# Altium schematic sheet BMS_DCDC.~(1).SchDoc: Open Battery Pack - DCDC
size A3; Date: 26/03/2019; Author: Morgane Vallée - Samuel Lesueur; Revision: 1.0; SheetNumber: 2; SheetTotal: 4
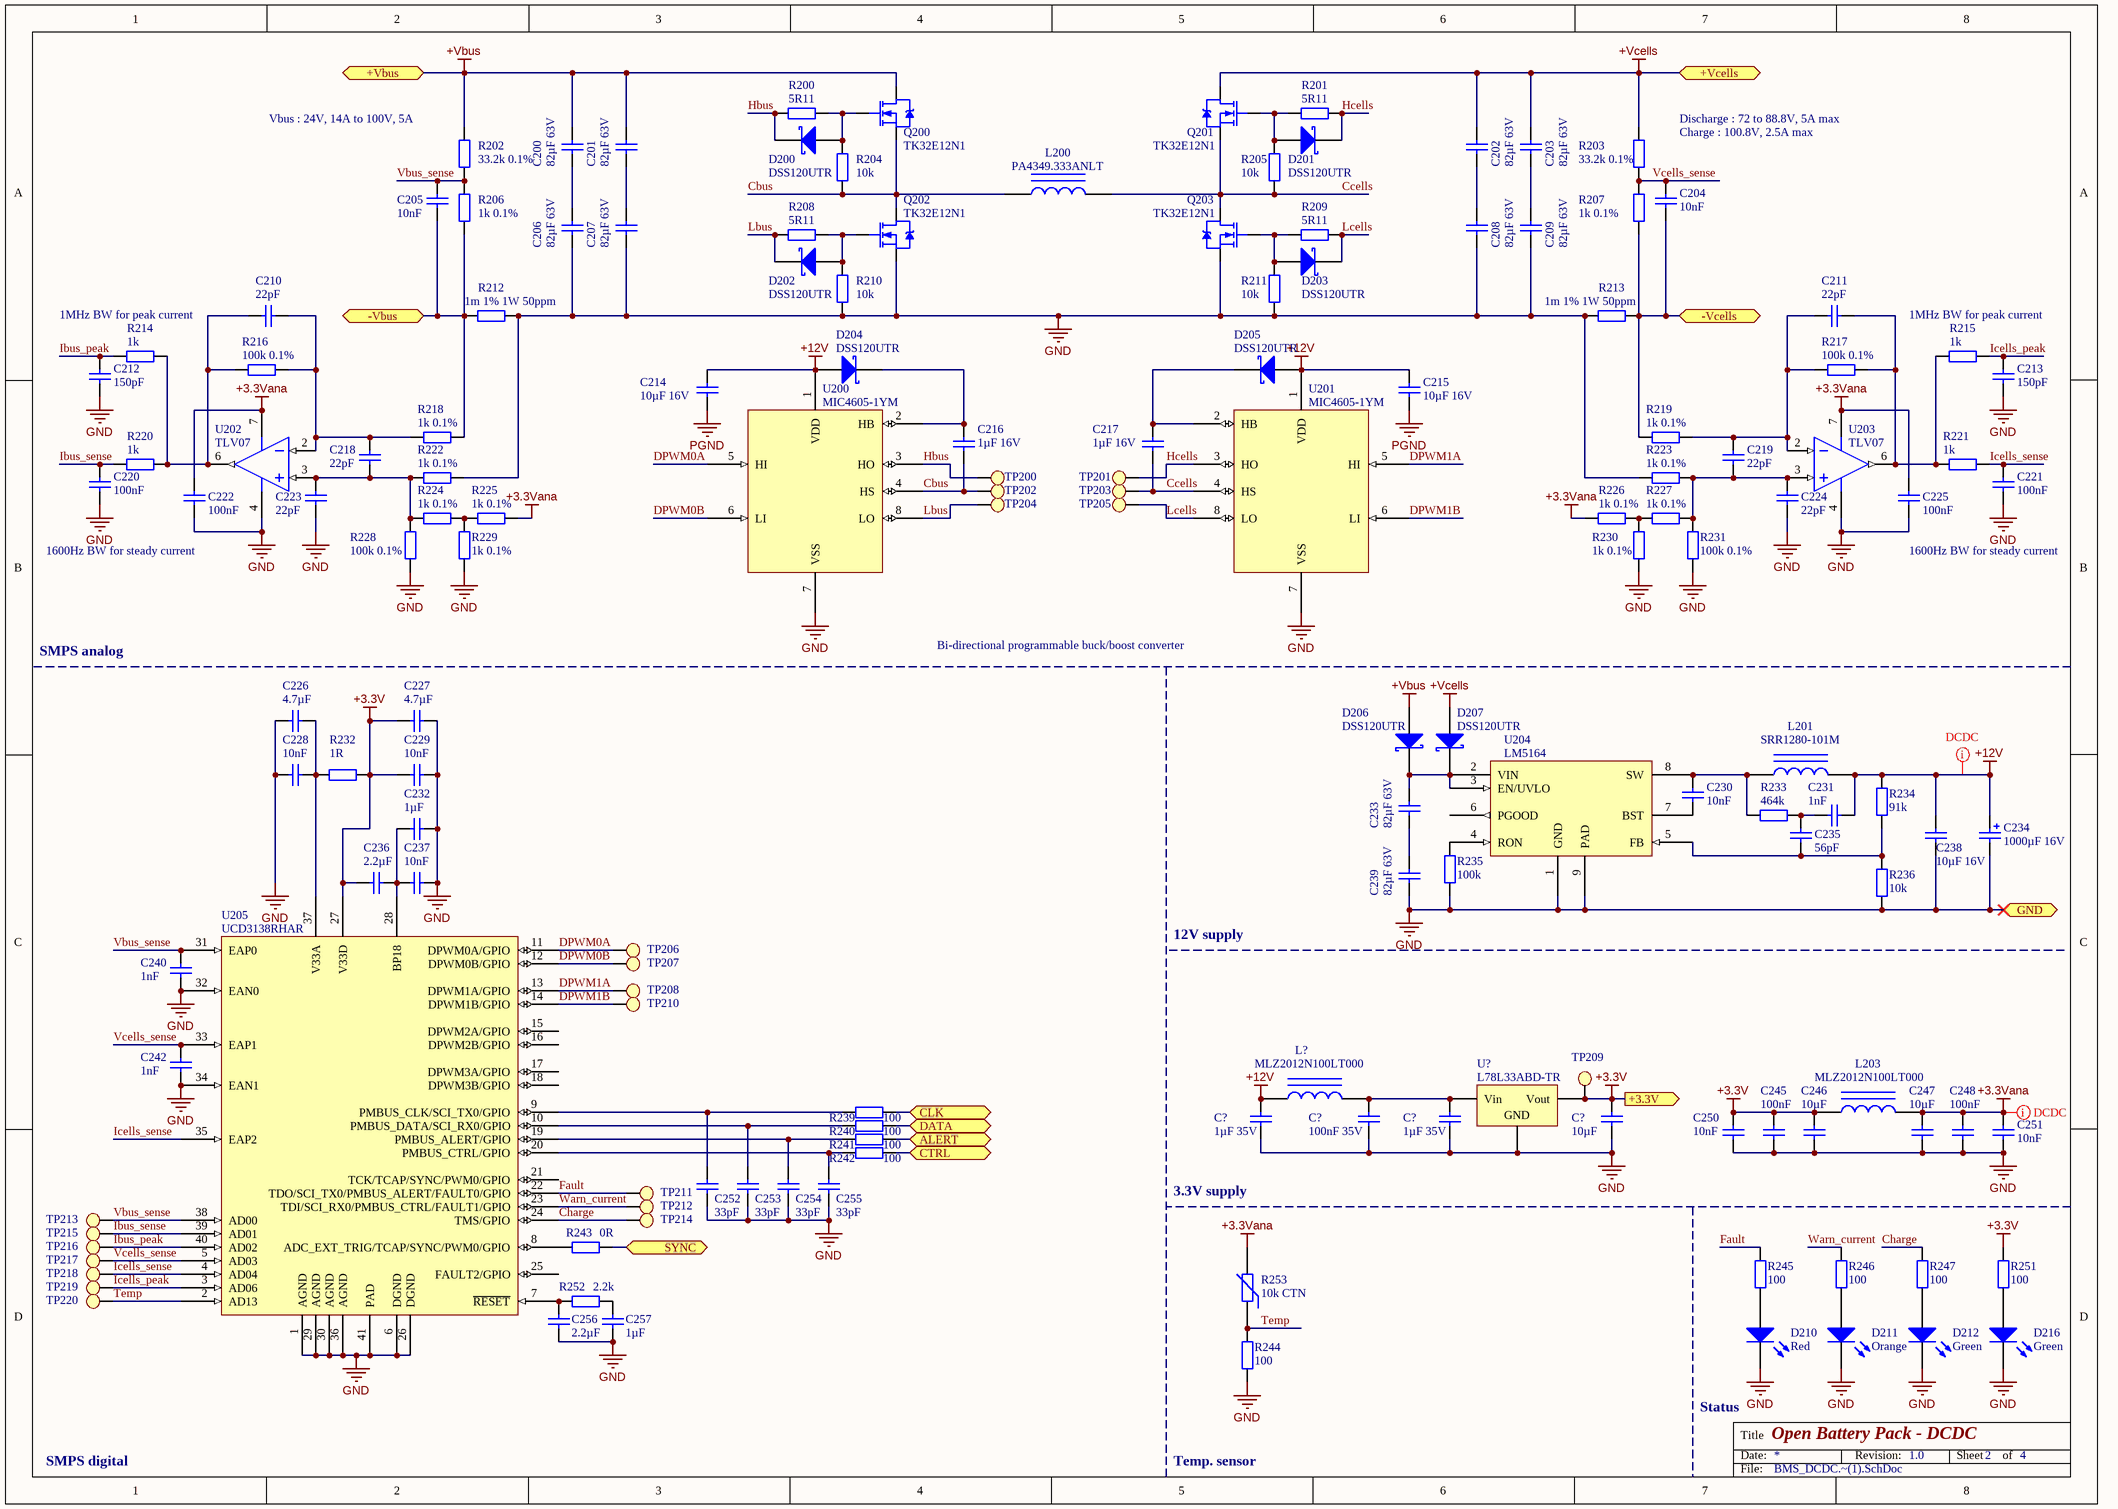
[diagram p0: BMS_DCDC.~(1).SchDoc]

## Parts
(Parts that share a designator on the sheet are numbered #1, #2 ... from top to bottom, then left to right.)
C200  82µF 63V  [CAP ALUM 10.3MM]
C201  82µF 63V  [CAP ALUM 10.3MM]
C202  82µF 63V  [CAP ALUM 10.3MM]
C203  82µF 63V  [CAP ALUM 10.3MM]
C204  10nF  [C0603]
C205  10nF  [C0603]
C206  82µF 63V  [CAP ALUM 10.3MM]
C207  82µF 63V  [CAP ALUM 10.3MM]
C208  82µF 63V  [CAP ALUM 10.3MM]
C209  82µF 63V  [CAP ALUM 10.3MM]
C210  22pF  [C0603]
C211  22pF  [C0603]
C212  150pF  [C0603]
C213  150pF  [C0603]
C214  10µF 16V  [C0805]
C215  10µF 16V  [C0805]
C216  1µF 16V  [C0603]
C217  1µF 16V  [C0603]
C218  22pF  [C0603]
C219  22pF  [C0603]
C220  100nF  [C0603]
C221  100nF  [C0603]
C222  100nF  [C0603]
C223  22pF  [C0603]
C224  22pF  [C0603]
C225  100nF  [C0603]
C226  4.7µF  [C0603]
C227  4.7µF  [C0603]
C228  10nF  [C0603]
C229  10nF  [C0603]
C230  10nF  [C0603]
C231  1nF  [C0603]
C232  1µF  [C0603]
C233  82µF 63V  [CAP ALUM 10.3MM]
C234  1000µF 16V  [CAP AL TH D10 L5 H17.5]
C235  56pF  [C0603]
C236  2.2µF  [C0603]
C237  10nF  [C0603]
C238  10µF 16V  [C0805]
C239  82µF 63V  [CAP ALUM 10.3MM]
C240  1nF  [C0603]
C242  1nF  [C0603]
C245  100nF  [C0603]
C246  10µF  [C0603]
C247  10µF  [C0603]
C248  100nF  [C0603]
C250  10nF  [C0603]
C251  10nF  [C0603]
C252  33pF  [C0603]
C253  33pF  [C0603]
C254  33pF  [C0603]
C255  33pF  [C0603]
C256  2.2µF  [C0603]
C257  1µF  [C0603]
C?#1  1µF 35V  [C0805]
C?#2  100nF 35V  [C0603]
C?#3  1µF 35V  [C0805]
C?#4  10µF  [C0603]
D200  DSS120UTR  [SOD123F]
D201  DSS120UTR  [SOD123F]
D202  DSS120UTR  [SOD123F]
D203  DSS120UTR  [SOD123F]
D204  DSS120UTR  [SOD123F]
D205  DSS120UTR  [SOD123F]
D206  DSS120UTR  [SOD123F]
D207  DSS120UTR  [SOD123F]
D210  Red  [LED 0603/1608]
D211  Orange  [LED 0603/1608]
D212  Green  [LED 0603/1608]
D216  Green  [LED 0603/1608]
L200  PA4349.333ANLT  [SELF_SMD_23.5x22]
L201  SRR1280-101M  [SELF_SMD_12.5x12.5]
L203  MLZ2012N100LT000  [C0805]
L?  MLZ2012N100LT000  [FER 0805/2012]
Q200  TK32E12N1  [TO220]
Q201  TK32E12N1  [TO220]
Q202  TK32E12N1  [TO220]
Q203  TK32E12N1  [TO220]
R200  5R11  [R0603]
R201  5R11  [R0603]
R202  33.2k 0.1%  [R0603]
R203  33.2k 0.1%  [R0603]
R204  10k  [R0603]
R205  10k  [R0603]
R206  1k 0.1%  [R0603]
R207  1k 0.1%  [R0603]
R208  5R11  [R0603]
R209  5R11  [R0603]
R210  10k  [R0603]
R211  10k  [R0603]
R212  1m 1% 1W 50ppm  [R1206]
R213  1m 1% 1W 50ppm  [R1206]
R214  1k  [R0603]
R215  1k  [R0603]
R216  100k 0.1%  [R0603]
R217  100k 0.1%  [R0603]
R218  1k 0.1%  [R0603]
R219  1k 0.1%  [R0603]
R220  1k  [R0603]
R221  1k  [R0603]
R222  1k 0.1%  [R0603]
R223  1k 0.1%  [R0603]
R224  1k 0.1%  [R0603]
R225  1k 0.1%  [R0603]
R226  1k 0.1%  [R0603]
R227  1k 0.1%  [R0603]
R228  100k 0.1%  [R0603]
R229  1k 0.1%  [R0603]
R230  1k 0.1%  [R0603]
R231  100k 0.1%  [R0603]
R232  1R  [R0603]
R233  464k  [R0603]
R234  91k  [R0603]
R235  100k  [R0603]
R236  10k  [R0603]
R239  100  [R0603]
R240  100  [R0603]
R241  100  [R0603]
R242  100  [R0603]
R243  0R  [R0603]
R244  100  [R0603]
R245  100  [R0603]
R246  100  [R0603]
R247  100  [R0603]
R251  100  [R0603]
R252  2.2k  [R0603]
R253  10k CTN  [R0603]
TP200  Test Point  [Test Point]  (value not drawn)
TP201  Test Point  [Test Point]  (value not drawn)
TP202  Test Point  [Test Point]  (value not drawn)
TP203  Test Point  [Test Point]  (value not drawn)
TP204  Test Point  [Test Point]  (value not drawn)
TP205  Test Point  [Test Point]  (value not drawn)
TP206  Test Point  [Test Point]  (value not drawn)
TP207  Test Point  [Test Point]  (value not drawn)
TP208  Test Point  [Test Point]  (value not drawn)
TP209  Test Point  [Test Point]  (value not drawn)
TP210  Test Point  [Test Point]  (value not drawn)
TP211  Test Point  [Test Point]  (value not drawn)
TP212  Test Point  [Test Point]  (value not drawn)
TP213  Test Point  [Test Point]  (value not drawn)
TP214  Test Point  [Test Point]  (value not drawn)
TP215  Test Point  [Test Point]  (value not drawn)
TP216  Test Point  [Test Point]  (value not drawn)
TP217  Test Point  [Test Point]  (value not drawn)
TP218  Test Point  [Test Point]  (value not drawn)
TP219  Test Point  [Test Point]  (value not drawn)
TP220  Test Point  [Test Point]  (value not drawn)
U200  MIC4605-1YM  [SOIC-8]
U201  MIC4605-1YM  [SOIC-8]
U202  TLV07  [SOIC-8]
U203  TLV07  [SOIC-8]
U204  LM5164  [R-PDSO-G8]
U205  UCD3138RHAR  [S-PVQFN-N40]
U?  L78L33ABD-TR  [ST SOIC-8N]

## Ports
+3.3V, +Vbus, +Vcells, -Vbus, -Vcells, ALERT (bidir), CLK (bidir), CTRL (bidir), DATA (bidir), GND, SYNC (bidir)

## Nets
+3.3V: C227.1 C229.1 C236.2 C245.1 C246.1 C250.1 C?#4.1 L203.1 R232.1 R251.1 TP209.1 U205.27(V33D) U?.3(Vout) ; port +3.3V
+3.3Vana: C222.1 C225.1 C247.1 C248.1 C251.1 L203.2 R225.1 R226.1 R253.2 U202.7(V+) U203.7(V+)
+12V: C214.2 C215.2 C231.2 C234.1 C238.1 C?#1.1 D204.1(A) D205.1(A) L201.2 L?.1 R234.1 U200.1(VDD) U201.1(VDD)
+Vbus: C200.2 C201.2 D206.1(A) Q200.3(D) R202.1 ; port +Vbus
+Vcells: C202.2 C203.2 D207.1(A) Q201.3(D) R203.1 ; port +Vcells
GND: C206.1 C207.1 C208.1 C209.1 C212.1 C213.1 C220.1 C221.1 C222.2 C223.1 C224.1 C225.2 C226.1 C227.2 C228.1 C229.2 C232.1 C234.2 C237.1 C238.2 C239.2 C240.2 C242.2 C245.2 C246.2 C247.2 C248.2 C250.2 C251.2 C252.2 C253.2 C254.2 C255.2 C256.2 C257.2 C?#1.2 C?#2.2 C?#3.2 C?#4.2 D210.2(K) D211.2(K) D212.2(K) D216.2(K) Q202.2(S) Q203.2(S) R210.2 R211.2 R212.1 R213.2 R222.1 R223.2 R228.2 R229.2 R230.2 R231.2 R235.2 R236.2 R244.2 U200.7(VSS) U201.7(VSS) U202.4(V-) U203.4(V-) U204.1(GND) U204.9(PAD) U205.1(AGND) U205.6(DGND) U205.26(DGND) U205.29(AGND) U205.30(AGND) U205.32(EAN0) U205.34(EAN1) U205.36(AGND) U205.41(PAD) U?.2(GND) ; port GND
PGND: C214.1 C215.1
-Vbus: C205.1 R206.2 R212.2 R218.1 ; port -Vbus
-Vcells: C204.1 R207.2 R213.1 R219.2 ; port -Vcells
ALERT: R241.2 ; port ALERT
Cbus: C216.1 L200.1 Q200.2(S) Q202.3(D) R204.2 TP202.1 U200.4(HS)
Ccells: C217.1 L200.2 Q201.2(S) Q203.3(D) R205.2 TP203.1 U201.4(HS)
Charge: R247.1 TP214.1 U205.24(TMS/GPIO)
CLK: R239.2 ; port CLK
CTRL: R242.2 ; port CTRL
DATA: R240.2 ; port DATA
DPWM0A: TP206.1 U200.5(HI) U205.11(DPWM0A/GPIO)
DPWM0B: TP207.1 U200.6(LI) U205.12(DPWM0B/GPIO)
DPWM1A: TP208.1 U201.5(HI) U205.13(DPWM1A/GPIO)
DPWM1B: TP210.1 U201.6(LI) U205.14(DPWM1B/GPIO)
Fault: R245.1 TP211.1 U205.22(TDO/SCI_TX0/PMBUS_ALERT/FAULT0/GPIO)
Hbus: D200.2(K) R200.2 TP200.1 U200.3(HO)
Hcells: D201.2(K) R201.1 TP201.1 U201.3(HO)
Ibus_peak: C212.2 R214.2 TP216.1 U205.40(AD02)
Ibus_sense: C220.2 R220.2 TP215.1 U205.39(AD01)
Icells_peak: C213.2 R215.1 TP219.1 U205.3(AD06)
Icells_sense: C221.2 R221.1 TP218.1 U205.4(AD04) U205.35(EAP2)
Lbus: D202.2(K) R208.2 TP204.1 U200.8(LO)
Lcells: D203.2(K) R209.1 TP205.1 U201.8(LO)
SYNC: R243.2 ; port SYNC
Temp: R244.1 R253.1 TP220.1 U205.2(AD13)
Vbus_sense: C205.2 C240.1 R202.2 R206.1 TP213.1 U205.31(EAP0) U205.38(AD00)
Vcells_sense: C204.2 C242.1 R203.2 R207.1 TP217.1 U205.5(AD03) U205.33(EAP1)
Warn_current: R246.1 TP212.1 U205.23(TDI/SCI_RX0/PMBUS_CTRL/FAULT1/GPIO)
NetC200_1: C200.1 C206.2
NetC201_1: C201.1 C207.2
NetC202_1: C202.1 C208.2
NetC203_1: C203.1 C209.2
NetC210_1: C210.1 R214.1 R216.2 R220.1 U202.6(OUT)
NetC210_2: C210.2 C218.2 R216.1 R218.2 U202.2(IN-)
NetC211_1: C211.1 C219.2 R217.2 R219.1 U203.2(IN-)
NetC211_2: C211.2 R215.2 R217.1 R221.2 U203.6(OUT)
NetC216_2: C216.2 D204.2(K) U200.2(HB)
NetC217_2: C217.2 D205.2(K) U201.2(HB)
NetC218_1: C218.1 C223.2 R222.2 R224.2 R228.1 U202.3(IN+)
NetC219_1: C219.1 C224.2 R223.1 R227.2 R231.1 U203.3(IN+)
NetC226_2: C226.2 C228.2 R232.2 U205.37(V33A)
NetC230_1: C230.1 L201.1 R233.1 U204.8(SW)
NetC230_2: C230.2 U204.7(BST)
NetC231_1: C231.1 C235.2 R233.2
NetC232_2: C232.2 C236.1 C237.2 U205.28(BP18)
NetC233_1: C233.1 D206.2(K) D207.2(K) U204.2(VIN) U204.3(EN/UVLO)
NetC233_2: C233.2 C239.1
NetC235_1: C235.1 R234.2 R236.1 U204.5(FB)
NetC252_1: C252.1 R239.1 U205.9(PMBUS_CLK/SCI_TX0/GPIO)
NetC253_1: C253.1 R240.1 U205.10(PMBUS_DATA/SCI_RX0/GPIO)
NetC254_1: C254.1 R241.1 U205.19(PMBUS_ALERT/GPIO)
NetC255_1: C255.1 R242.1 U205.20(PMBUS_CTRL/GPIO)
NetC256_1: C256.1 R252.1 U205.7(~{RESET})
NetC257_1: C257.1 R252.2
NetC?#2_1: C?#2.1 C?#3.1 L?.2 U?.1(Vin)
NetD200_1: D200.1(A) Q200.1(G) R200.1 R204.1
NetD201_1: D201.1(A) Q201.1(G) R201.2 R205.1
NetD202_1: D202.1(A) Q202.1(G) R208.1 R210.1
NetD203_1: D203.1(A) Q203.1(G) R209.2 R211.1
NetD210_1: D210.1(A) R245.2
NetD211_1: D211.1(A) R246.2
NetD212_1: D212.1(A) R247.2
NetD216_1: D216.1(A) R251.2
NetR224_1: R224.1 R225.2 R229.1
NetR226_2: R226.2 R227.1 R230.1
NetR235_1: R235.1 U204.4(RON)
NetR243_1: R243.1 U205.8(ADC_EXT_TRIG/TCAP/SYNC/PWM0/GPIO)

Not connected (* = marked no-connect by the designer): U204 6(PGOOD); U205 15(DPWM2A/GPIO) 16(DPWM2B/GPIO) 17(DPWM3A/GPIO) 18(DPWM3B/GPIO) 21(TCK/TCAP/SYNC/PWM0/GPIO) 25(FAULT2/GPIO)

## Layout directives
net class DCDC: +3.3Vana, +12V

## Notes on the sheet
- (near R202) Vbus : 24V, 14A to 100V, 5A
- (near R203) Discharge : 72 to 88.8V, 5A max
- Charge : 100.8V, 2.5A max
- 1MHz BW for peak current
- 1600Hz BW for steady current
- Bi-directional programmable buck/boost converter
- SMPS analog
- 12V supply
- 3.3V supply
- Status
- SMPS digital
- Temp. sensor

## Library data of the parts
C200-C233 C235-C240 C242 C245-C248 C250-C257 C?#1-C?#4 = Cap: Capacitor
C234 = Cap Pol1: Polarized Capacitor (Radial)
D200-D207 = D Schottky: Schottky Diode; pin to pad: 1>1+3
D210-D212 D216 = LED2: Typical RED, GREEN, YELLOW, AMBER GaAs LED
L200 L201 L203 L? = Inductor Iron: Magnetic-Core Inductor
Q200-Q203 = MOSFET_N
R200-R236 R239-R247 R251 R252 = Res2: Resistor
R253 = Res Varistor: Varistor (Voltage-Sensitive Resistor)
U200 U201 = MIC4605-1YM: 85V Half-Bridge MOSFET Driver with Adaptive Dead Time  and Shoot-Through Protection
U202 U203 = TLV07: 36-V Precision,Rail-to-RailOutputOperationalAmplifier
U204 = LM5164: 100-V Input, 1-A synchronous buck DC/DC converter with ultra-low IQ
U205 = UCD3138RHAR: Highly Integrated Digital Controller for Isolated Power with 3 Feedback Loops and 8 DPWM Outputs, 40pins
U? = Volt Reg: Voltage Regulator; pin to pad: 1>8 2>2+3+6+7 3>1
